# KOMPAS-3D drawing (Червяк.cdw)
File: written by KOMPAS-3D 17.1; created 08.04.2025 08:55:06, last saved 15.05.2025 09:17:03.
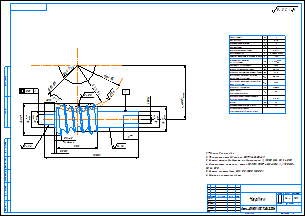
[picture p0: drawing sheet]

Sheet 1: A2, landscape

Title block, sheet 1: name: Червяк; material: Сталь 40ХН2МА ГОСТ 4543-2016; mass: 1,4 г; sheets: 1; sheet format: A2; stored path: C:\Users\DymLe\Documents\Рабочая папка\чертежи\3В86\чертежи для Вани\ЕИЛЮ.722552.001.cdw
Table, sheet 1:
  1877829139

Views: Вид червяка, Вид 1, Снизу
Referenced files in C:\Users\DymLe\Documents\Рабочая папка\чертежи\3В86\чертежи для Вани\: ЕИЛЮ.722552.001.m3d
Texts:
  Ячейка таблицы
  Обозначение чертежа
  сопряженного червячного колеса
  Делительный диаметр колеса
  Модуль
  Максимальный делительный угол
  подъема линии витка
  Число зубьев
  сопряженного колеса
  Межосевое расстояние
  Предельные отклонения межосевого
  угла в обработке
  Предельные смещения средней
  плоскости в обработке
  Допуск на погрешность профиля витка
  Допуск на отклонение шага
  Высота до хорды витка
  Делительная толщина
  по хорде витка
  Степень точности по ГОСТ 16502-83
  Исходный червяк
  Направление линии витка
  Высота витка
  Делительный диаметр
  Число витков
  f xc1
  f Px
  ГОСТ 24438-80
  правое
  GAU
  Ra 3,2 ( )
  Ra 6.3
  Ra 3,2
  Ra 0,8
  Ra 1,6
  ЕИЛЮ.722552.001
  *Размер для справок.
  Технические требования по ОСТ 92-0400-69.
  Деталь термообработать с обеспечением  в 1000 МПа, 30...34 HRC.
  Допускается материал:  сталь 30ХГСА ГОСТ 4543-2016,  в 950 МПа,
  30...34 HRC.
  Деталь азотировать h0,3...0,5; 1000...1200 HV.
  Массу не контролировать.
  gliv
  BOSimple***Material:fd48d8f1-45f7-47f0-a9f1-b1ec4985fdbe
Dimensions and other numbers on the sheet: 1; 3; 1,5; 2; 18,5; 16; 0,5; 7 10'48"; 32; 10 0,03; 0,072; 0,018; 0,443; 0,707 -0,22 -0,3; 7-B; 4; 8; 0,8; 2 фаски; 4,9; 6,21; 7,24; 10,57; 9,116; 17,132; 8,116; 0,01; 10:1; 1,4 г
